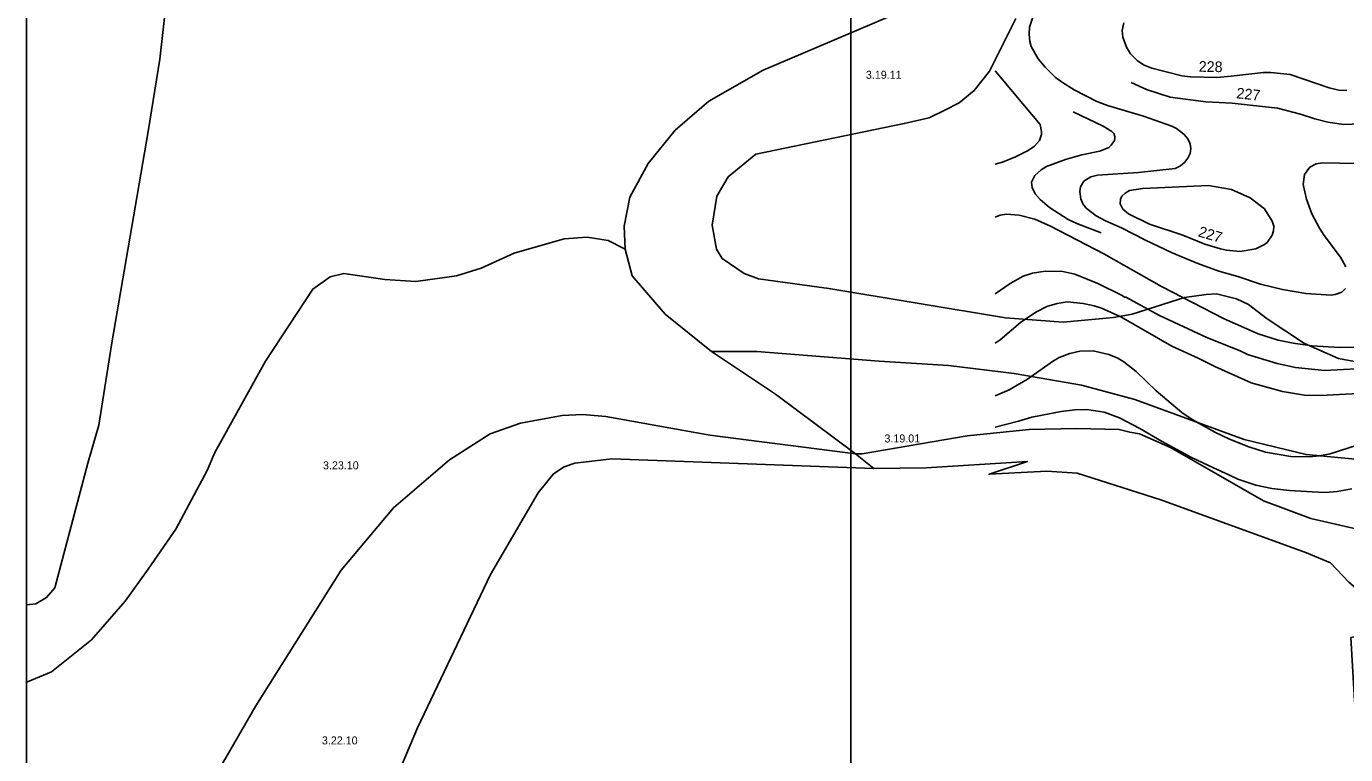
# Model space of a CAD drawing. Extents: x -662500 to -655523, y -1056000 to -1049993.
# Drawn here: x -662500 to -661264, y -1053965 to -1053283 of the extents above; entities that cross this region are included whole.
import ezdxf

# ---------------------------------------------------------------- set-up
doc = ezdxf.new("R2010")
doc.units = 0
for name, color, linetype in [('Vrstva 24', 7, 'Continuous'), ('Vrstva 7', 7, 'Continuous'), ('Vrstva 9', 7, 'Continuous')]:
    doc.layers.add(name, color=color, linetype=linetype)

msp = doc.modelspace()

# ---------------------------------------------------------------- linework, layer by layer
at = {"layer": 'Vrstva 24'}
for points in [[(-662500, -1053824.9), (-662500, -1053023.2)], [(-662500, -1053824.9), (-662491, -1053824), (-662481, -1053818), (-662473.5, -1053809), (-662442.5, -1053692), (-662432, -1053656.5), (-662420, -1053579.5), (-662386, -1053381.5), (-662375, -1053313.5), (-662363.5, -1053210.5), (-662350.5, -1053159.3)], [(-661668, -1053263.5), (-661809.5, -1053324), (-661860.5, -1053353), (-661892, -1053380), (-661917.5, -1053411.5), (-661934.5, -1053443), (-661940, -1053470), (-661939, -1053491.5)], [(-661252, -1053597.5), (-661270.5, -1053594), (-661302.5, -1053580), (-661337.5, -1053557), (-661355, -1053543.5), (-661366, -1053538), (-661385, -1053533.5), (-661394.5, -1053534), (-661415, -1053537), (-661464, -1053552.5), (-661481.5, -1053555.5), (-661528.5, -1053560), (-661582.5, -1053556), (-661748, -1053528.5), (-661814, -1053519.5), (-661827.5, -1053514.5), (-661848, -1053500.5), (-661853.5, -1053491.5), (-661857.5, -1053469), (-661853, -1053442), (-661842.5, -1053424), (-661816.5, -1053402.5), (-661677.5, -1053374), (-661654, -1053368.5), (-661639.5, -1053361.5), (-661626, -1053354.5), (-661612, -1053343), (-661597.5, -1053325), (-661573, -1053275.5)], [(-661939, -1053491.5), (-661955, -1053483.5), (-661974.5, -1053480.5), (-661996, -1053482), (-662043, -1053495.5), (-662074, -1053509.5), (-662097, -1053516.5), (-662135, -1053522), (-662164, -1053520), (-662202.5, -1053514.5), (-662215.5, -1053517.5), (-662231.5, -1053529), (-662276, -1053596.5), (-662323.5, -1053682), (-662330.5, -1053699), (-662360, -1053754), (-662386, -1053791.5), (-662407.5, -1053821.5), (-662439, -1053857.5), (-662476.5, -1053887.5), (-662499, -1053897), (-662500, -1053897.1)], [(-661858, -1053587.5), (-661901.5, -1053552.5), (-661932.5, -1053516.5), (-661939, -1053491.5)], [(-661723, -1053683.5), (-661798, -1053627.5), (-661858, -1053587.5)], [(-661185.5, -1053695), (-661301, -1053684), (-661359, -1053670), (-661461.5, -1053632.5), (-661511.5, -1053619), (-661574.5, -1053608), (-661636, -1053600.5), (-661701, -1053596.5), (-661815.5, -1053587.5), (-661858, -1053587.5)], [(-661723, -1053683.5), (-661859.5, -1053666), (-661957, -1053648.5), (-661979, -1053646.5), (-661998, -1053647.5), (-662037, -1053654.5), (-662065.5, -1053664.5), (-662103.5, -1053689), (-662156, -1053734), (-662205, -1053792.5), (-662285, -1053919.5), (-662331.5, -1054000), (-662360.5, -1054035.5), (-662385.5, -1054080.5), (-662405, -1054139), (-662415.5, -1054202), (-662415, -1054265), (-662409, -1054319), (-662411, -1054350.5), (-662415, -1054362.5)], [(-661001.5, -1053773), (-661007, -1053832.5), (-661011, -1053841.5), (-661017, -1053844.5), (-661056, -1053821), (-661089.5, -1053807), (-661175, -1053776.5), (-661238, -1053757.5), (-661296.5, -1053744), (-661341, -1053727.5), (-661428, -1053677.5), (-661441.5, -1053671.5), (-661457, -1053664.5), (-661466, -1053663), (-661476, -1053660.5), (-661516, -1053659.5), (-661560.5, -1053660.5), (-661618.5, -1053666.5), (-661717, -1053683.5), (-661723, -1053683.5)], [(-661706, -1053697), (-661951.5, -1053688), (-661986, -1053692), (-661996, -1053695.5), (-662006, -1053702), (-662020.5, -1053720), (-662065, -1053796.5), (-662133.5, -1053940), (-662158.8, -1054000)], [(-661706, -1053697), (-661723, -1053683.5)], [(-661246.7, -1054000), (-661255.5, -1053914.5), (-661259, -1053855.5), (-661241.5, -1053852), (-661175.5, -1053833), (-661167, -1053828.5), (-661160, -1053819.5), (-661160.5, -1053809.5), (-661167, -1053798.5), (-661180.5, -1053790.5), (-661197, -1053787.5), (-661206.5, -1053790), (-661238, -1053823), (-661261, -1053803.5), (-661278, -1053785.5), (-661300.5, -1053776), (-661437, -1053726.5), (-661515.5, -1053701.5), (-661544, -1053699.5), (-661598, -1053702.5), (-661562, -1053690.5), (-661657, -1053696.5), (-661706, -1053697)], [(-662500, -1053897.1), (-662500, -1053824.9)], [(-662500, -1054302.2), (-662500, -1054000), (-662500, -1053897.1)]]:
    msp.add_lwpolyline(points, dxfattribs=at)
at = {"layer": 'Vrstva 7'}
for p, q in [((-661560, -1053283.5), (-661557.1, -1053274.4)), ((-661471.8, -1053279.7), (-661473.2, -1053286.9)), ((-661560.5, -1053290.3), (-661560, -1053283.5)), ((-661559.8, -1053297.1), (-661560.5, -1053290.3)), ((-661473.2, -1053286.9), (-661472.8, -1053293.1)), ((-661472.8, -1053293.1), (-661469.1, -1053302.5)), ((-661558.5, -1053301.6), (-661559.8, -1053297.1)), ((-661551.9, -1053313.4), (-661558.5, -1053301.6)), ((-661469.1, -1053302.5), (-661465.4, -1053308.7)), ((-661545.5, -1053321.2), (-661551.9, -1053313.4)), ((-661465.4, -1053308.7), (-661459.3, -1053314.8)), ((-661459.3, -1053314.8), (-661453.2, -1053318.8)), ((-661550.2, -1053374.9), (-661592.2, -1053324.6)), ((-661535.7, -1053330.8), (-661545.5, -1053321.2)), ((-661529.3, -1053335.6), (-661535.7, -1053330.8)), ((-661453.2, -1053318.8), (-661445.6, -1053322.2)), ((-661445.6, -1053322.2), (-661417.5, -1053329.3)), ((-661417.5, -1053329.3), (-661409.3, -1053330.2)), ((-661409.3, -1053330.2), (-661384.7, -1053330.7)), ((-661384.7, -1053330.7), (-661371.1, -1053329.7)), ((-661371.1, -1053329.7), (-661340.7, -1053326.1)), ((-661340.7, -1053326.1), (-661333.9, -1053326)), ((-661333.9, -1053326), (-661315.9, -1053328)), ((-661315.9, -1053328), (-661279.2, -1053340.6)), ((-661518.4, -1053342.4), (-661529.3, -1053335.6)), ((-661496.9, -1053353.3), (-661518.4, -1053342.4)), ((-661464.7, -1053335.5), (-661450.4, -1053342.1)), ((-661450.4, -1053342.1), (-661428.2, -1053349.2)), ((-661279.2, -1053340.6), (-661270.4, -1053342.6)), ((-661270.4, -1053342.6), (-661262.8, -1053343.1)), ((-661487, -1053357), (-661496.9, -1053353.3)), ((-661428.2, -1053349.2), (-661394.9, -1053353.6)), ((-661394.9, -1053353.6), (-661370.1, -1053354.9)), ((-661370.1, -1053354.9), (-661327.7, -1053359.4)), ((-661491.2, -1053376.4), (-661519.1, -1053363.1)), ((-661453.2, -1053366.9), (-661487, -1053357)), ((-661426.7, -1053376.4), (-661453.2, -1053366.9)), ((-661327.7, -1053359.4), (-661306.1, -1053365)), ((-661306.1, -1053365), (-661292.8, -1053369.5)), ((-661548.8, -1053381.3), (-661550.2, -1053374.9)), ((-661483.1, -1053381.3), (-661491.2, -1053376.4)), ((-661422.4, -1053378.7), (-661426.7, -1053376.4)), ((-661415.6, -1053383.8), (-661422.4, -1053378.7)), ((-661292.8, -1053369.5), (-661280.6, -1053372.5)), ((-661280.6, -1053372.5), (-661265.6, -1053374.7)), ((-661265.6, -1053374.7), (-661250, -1053374.2)), ((-661555.3, -1053395), (-661550.6, -1053389.8)), ((-661550.6, -1053389.8), (-661548.9, -1053384.1)), ((-661548.9, -1053384.1), (-661548.8, -1053381.3)), ((-661483.5, -1053394.3), (-661481.9, -1053392.1)), ((-661481, -1053383.4), (-661483.1, -1053381.3)), ((-661481.9, -1053392.1), (-661480.6, -1053389.8)), ((-661480.3, -1053386.1), (-661481, -1053383.4)), ((-661480.6, -1053389.8), (-661480.1, -1053387.7)), ((-661480.1, -1053387.7), (-661480.3, -1053386.1)), ((-661411.9, -1053388.3), (-661415.6, -1053383.8)), ((-661409.7, -1053392.9), (-661411.9, -1053388.3)), ((-661409, -1053397.4), (-661409.7, -1053392.9)), ((-661585.3, -1053410), (-661573.1, -1053405.2)), ((-661573.1, -1053405.2), (-661561.2, -1053399.3)), ((-661561.2, -1053399.3), (-661555.3, -1053395)), ((-661526.4, -1053407.6), (-661511.1, -1053403.4)), ((-661511.1, -1053403.4), (-661494.1, -1053399.8)), ((-661494.1, -1053399.8), (-661485.7, -1053396.3)), ((-661485.7, -1053396.3), (-661483.5, -1053394.3)), ((-661411.9, -1053406.5), (-661409.6, -1053402)), ((-661409.6, -1053402), (-661409, -1053397.4)), ((-661592.2, -1053412.1), (-661585.3, -1053410)), ((-661555.1, -1053422.6), (-661549.3, -1053417.3)), ((-661549.3, -1053417.3), (-661544.1, -1053414.3)), ((-661544.1, -1053414.3), (-661526.4, -1053407.6)), ((-661458.1, -1053419.8), (-661423.5, -1053416.1)), ((-661423.5, -1053416.1), (-661418.7, -1053413.7)), ((-661418.7, -1053413.7), (-661415, -1053410.5)), ((-661415, -1053410.5), (-661411.9, -1053406.5)), ((-661297.4, -1053414.9), (-661302.3, -1053421.8)), ((-661291.4, -1053411.6), (-661297.4, -1053414.9)), ((-661285.5, -1053410.6), (-661291.4, -1053411.6)), ((-661253.7, -1053411.3), (-661285.5, -1053410.6)), ((-661558.3, -1053429), (-661555.1, -1053422.6)), ((-661557.7, -1053434), (-661558.3, -1053429)), ((-661512.2, -1053433.1), (-661509.2, -1053428)), ((-661509.2, -1053428), (-661502.6, -1053423.8)), ((-661502.6, -1053423.8), (-661496.3, -1053422.4)), ((-661496.3, -1053422.4), (-661458.1, -1053419.8)), ((-661302.3, -1053421.8), (-661303.6, -1053431.1)), ((-661554.7, -1053439.8), (-661557.7, -1053434)), ((-661550, -1053445), (-661554.7, -1053439.8)), ((-661513.1, -1053437.7), (-661512.2, -1053433.1)), ((-661512.1, -1053444.5), (-661513.1, -1053437.7)), ((-661474.8, -1053444.8), (-661473.7, -1053442.1)), ((-661473.7, -1053442.1), (-661470.5, -1053439.1)), ((-661470.5, -1053439.1), (-661466.3, -1053436.7)), ((-661466.3, -1053436.7), (-661454, -1053434.8)), ((-661454, -1053434.8), (-661392.3, -1053432.1)), ((-661392.3, -1053432.1), (-661370.8, -1053435.7)), ((-661370.8, -1053435.7), (-661353.5, -1053443.5)), ((-661303.6, -1053431.1), (-661300.6, -1053444.8)), ((-661541.4, -1053452.7), (-661550, -1053445)), ((-661523.8, -1053463.7), (-661541.4, -1053452.7)), ((-661510.1, -1053449), (-661512.1, -1053444.5)), ((-661507.1, -1053453.3), (-661510.1, -1053449)), ((-661497.5, -1053460.5), (-661507.1, -1053453.3)), ((-661475.2, -1053449.3), (-661474.8, -1053444.8)), ((-661472.5, -1053454.2), (-661475.2, -1053449.3)), ((-661467.3, -1053458.6), (-661472.5, -1053454.2)), ((-661353.5, -1053443.5), (-661340, -1053453.7)), ((-661340, -1053453.7), (-661332.6, -1053465.4)), ((-661300.6, -1053444.8), (-661295.7, -1053458.4)), ((-661592.2, -1053461.5), (-661587.6, -1053459.9)), ((-661587.6, -1053459.9), (-661581.6, -1053458.8)), ((-661581.6, -1053458.8), (-661569.7, -1053459.8)), ((-661569.7, -1053459.8), (-661555.1, -1053463.6)), ((-661555.1, -1053463.6), (-661540.3, -1053470)), ((-661515.6, -1053467.6), (-661523.8, -1053463.7)), ((-661489, -1053465), (-661497.5, -1053460.5)), ((-661473.8, -1053471.5), (-661489, -1053465)), ((-661447.6, -1053468.1), (-661467.3, -1053458.6)), ((-661332.6, -1053465.4), (-661331.2, -1053470)), ((-661295.7, -1053458.4), (-661288.3, -1053472)), ((-661540.3, -1053470), (-661490.4, -1053495.9)), ((-661492.8, -1053476.2), (-661515.6, -1053467.6)), ((-661451.3, -1053483.2), (-661473.8, -1053471.5)), ((-661416.4, -1053478.6), (-661447.6, -1053468.1)), ((-661395.7, -1053486.8), (-661416.4, -1053478.6)), ((-661332.8, -1053478.5), (-661337.5, -1053485.4)), ((-661331.5, -1053474.5), (-661332.8, -1053478.5)), ((-661331.2, -1053470), (-661331.5, -1053474.5)), ((-661288.3, -1053472), (-661283.9, -1053478.8)), ((-661283.9, -1053478.8), (-661268.7, -1053499.2)), ((-661426.3, -1053495.1), (-661451.3, -1053483.2)), ((-661381, -1053491.2), (-661395.7, -1053486.8)), ((-661375.6, -1053492.5), (-661381, -1053491.2)), ((-661348.1, -1053491.2), (-661362.7, -1053493.8)), ((-661339.9, -1053487.4), (-661348.1, -1053491.2)), ((-661337.5, -1053485.4), (-661339.9, -1053487.4)), ((-661490.4, -1053495.9), (-661436.5, -1053526.5)), ((-661402.5, -1053505.1), (-661426.3, -1053495.1)), ((-661362.7, -1053493.8), (-661375.6, -1053492.5)), ((-661268.7, -1053499.2), (-661263.6, -1053508.2)), ((-661566.1, -1053517), (-661557.3, -1053514.1)), ((-661557.3, -1053514.1), (-661545.4, -1053512.1)), ((-661545.4, -1053512.1), (-661528.9, -1053512.6)), ((-661528.9, -1053512.6), (-661517.6, -1053515.2)), ((-661517.6, -1053515.2), (-661496, -1053523.8)), ((-661382.7, -1053512.1), (-661402.5, -1053505.1)), ((-661364.8, -1053517.2), (-661382.7, -1053512.1)), ((-661592.2, -1053533.4), (-661578.2, -1053523.8)), ((-661578.2, -1053523.8), (-661566.1, -1053517)), ((-661496, -1053523.8), (-661473.4, -1053535)), ((-661436.5, -1053526.5), (-661377.6, -1053557)), ((-661343.8, -1053524.3), (-661364.8, -1053517.2)), ((-661323.2, -1053529.4), (-661343.8, -1053524.3)), ((-661263.9, -1053528.6), (-661267.6, -1053531.9)), ((-661534.3, -1053542.4), (-661524.7, -1053541.1)), ((-661524.7, -1053541.1), (-661509.7, -1053542.5)), ((-661473.4, -1053535), (-661471.1, -1053536.7)), ((-661471.1, -1053536.7), (-661469.7, -1053536.7)), ((-661469.7, -1053536.7), (-661438.2, -1053553.9)), ((-661301.3, -1053533.3), (-661323.2, -1053529.4)), ((-661277.5, -1053534.7), (-661301.3, -1053533.3)), ((-661273.6, -1053534.2), (-661277.5, -1053534.7)), ((-661267.6, -1053531.9), (-661273.6, -1053534.2)), ((-661568.5, -1053560.4), (-661554.1, -1053550.5)), ((-661554.1, -1053550.5), (-661543.9, -1053545.4)), ((-661543.9, -1053545.4), (-661534.3, -1053542.4)), ((-661509.7, -1053542.5), (-661499.4, -1053544.7)), ((-661499.4, -1053544.7), (-661492.6, -1053546.8)), ((-661492.6, -1053546.8), (-661474.4, -1053554.9)), ((-661587.7, -1053576.7), (-661568.5, -1053560.4)), ((-661474.4, -1053554.9), (-661426.6, -1053582.4)), ((-661438.2, -1053553.9), (-661393.3, -1053574.6)), ((-661377.6, -1053557), (-661345.8, -1053570.9)), ((-661592.2, -1053579.8), (-661587.7, -1053576.7)), ((-661393.3, -1053574.6), (-661362.8, -1053586.9)), ((-661345.8, -1053570.9), (-661327.1, -1053577)), ((-661327.1, -1053577), (-661313.2, -1053579.8)), ((-661532.2, -1053593), (-661522.4, -1053589.3)), ((-661522.4, -1053589.3), (-661512.8, -1053587.2)), ((-661512.8, -1053587.2), (-661500.3, -1053586.8)), ((-661500.3, -1053586.8), (-661485.8, -1053590.2)), ((-661485.8, -1053590.2), (-661477.3, -1053593.8)), ((-661426.6, -1053582.4), (-661402.1, -1053593.6)), ((-661362.8, -1053586.9), (-661355.9, -1053590.3)), ((-661355.9, -1053590.3), (-661328, -1053598.7)), ((-661313.2, -1053579.8), (-661295.4, -1053582.1)), ((-661295.4, -1053582.1), (-661269.6, -1053583.9)), ((-661269.6, -1053583.9), (-661255.7, -1053583.5)), ((-661562.1, -1053613.5), (-661537.7, -1053596.2)), ((-661537.7, -1053596.2), (-661532.2, -1053593)), ((-661477.3, -1053593.8), (-661471.7, -1053597.1)), ((-661471.7, -1053597.1), (-661460.3, -1053606.2)), ((-661402.1, -1053593.6), (-661386.6, -1053601.6)), ((-661386.6, -1053601.6), (-661352.3, -1053616.7)), ((-661328, -1053598.7), (-661311, -1053602.5)), ((-661311, -1053602.5), (-661283.8, -1053605.3)), ((-661283.8, -1053605.3), (-661220.3, -1053602.1)), ((-661579.1, -1053623.3), (-661562.1, -1053613.5)), ((-661460.3, -1053606.2), (-661441.5, -1053624.4)), ((-661592.2, -1053629), (-661579.1, -1053623.3)), ((-661441.5, -1053624.4), (-661417.3, -1053644.7)), ((-661352.3, -1053616.7), (-661322.9, -1053625)), ((-661322.9, -1053625), (-661302.5, -1053628.3)), ((-661287.2, -1053628.6), (-661246.3, -1053626.6)), ((-661302.5, -1053628.3), (-661287.2, -1053628.6)), ((-661570.3, -1053652.9), (-661557.8, -1053649)), ((-661557.8, -1053649), (-661530.5, -1053643.7)), ((-661530.5, -1053643.7), (-661517.6, -1053642.2)), ((-661517.6, -1053642.2), (-661506.5, -1053641.7)), ((-661506.5, -1053641.7), (-661490.1, -1053644.3)), ((-661490.1, -1053644.3), (-661475.8, -1053649.7)), ((-661475.8, -1053649.7), (-661456.6, -1053659.6)), ((-661417.3, -1053644.7), (-661407.6, -1053651.2)), ((-661407.6, -1053651.2), (-661386.4, -1053663)), ((-661592.2, -1053658.4), (-661570.3, -1053652.9)), ((-661456.6, -1053659.6), (-661436.5, -1053671.4)), ((-661386.4, -1053663), (-661372.8, -1053669.7)), ((-661436.5, -1053671.4), (-661408.2, -1053686.8)), ((-661372.8, -1053669.7), (-661354.6, -1053676.9)), ((-661354.6, -1053676.9), (-661339, -1053681.8)), ((-661278.4, -1053683.3), (-661244.2, -1053672.5)), ((-661408.2, -1053686.8), (-661387.6, -1053696.4)), ((-661339, -1053681.8), (-661315.2, -1053685.8)), ((-661315.2, -1053685.8), (-661298.2, -1053686.2)), ((-661298.2, -1053686.2), (-661288.3, -1053685.2)), ((-661288.3, -1053685.2), (-661278.4, -1053683.3)), ((-661387.6, -1053696.4), (-661373.3, -1053703)), ((-661373.3, -1053703), (-661364.8, -1053707.2)), ((-661364.8, -1053707.2), (-661348.1, -1053712.6)), ((-661348.1, -1053712.6), (-661333.2, -1053715.7)), ((-661333.2, -1053715.7), (-661316.6, -1053717.6)), ((-661316.6, -1053717.6), (-661295.4, -1053719.1)), ((-661295.4, -1053719.1), (-661283, -1053719.7)), ((-661283, -1053719.7), (-661271.8, -1053718.7)), ((-661271.8, -1053718.7), (-661258.2, -1053716.3))]:
    msp.add_line(p, q, dxfattribs=at)
at = {"layer": 'Vrstva 9'}
msp.add_line((-661727.5, -1054263.7), (-661727.5, -1050947.2), dxfattribs=at)

# ---------------------------------------------------------------- texts
at = {"layer": 'Vrstva 24'}
for s, p in [('3.19.11', (-661713.4, -1053332)), ('3.19.01', (-661696, -1053672.7)), ('3.23.10', (-662222.1, -1053697.9)), ('3.22.10', (-662223.1, -1053955.6))]:
    msp.add_text(s, height=7.5, dxfattribs=at).set_placement(p)
at = {"layer": 'Vrstva 7'}
for s, rotation, p in [('228', 359.0103, (-661401.6, -1053325.4)), ('227', 353.8911, (-661366.6, -1053350.2)), ('227', 343.4032, (-661402.7, -1053479.5))]:
    msp.add_text(s, height=10, rotation=rotation, dxfattribs=at).set_placement(p)

doc.saveas('drawing.dxf')
